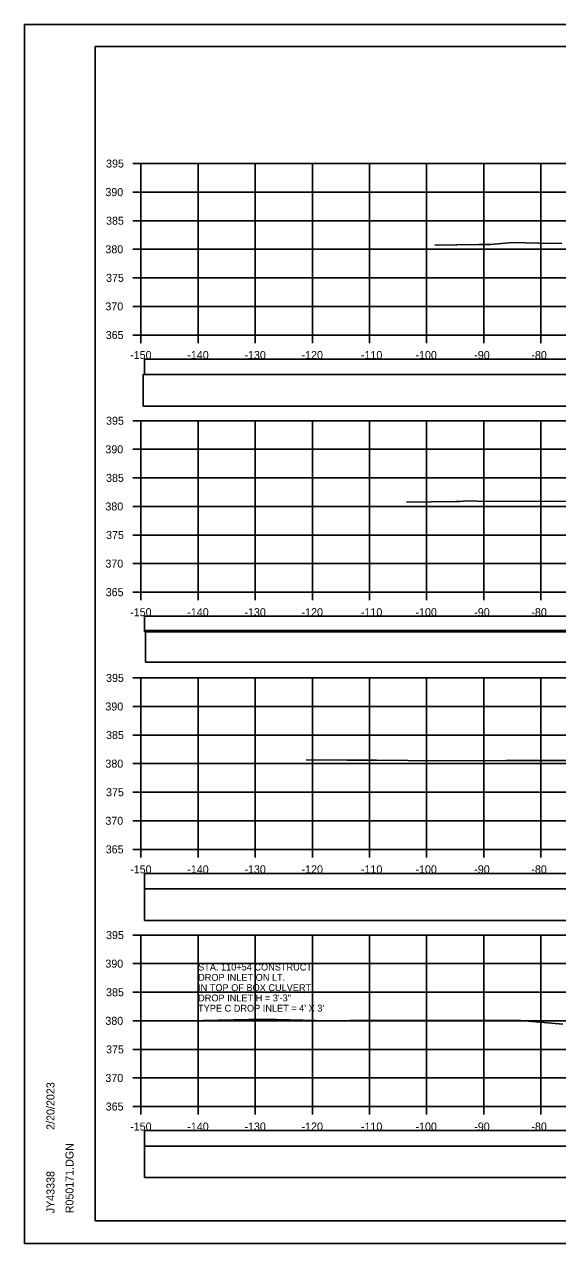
# Model space of a CAD drawing. Extents: x -37291014 to -37290680, y -936053 to -933067.
# Drawn here: x -37291013.5 to -37290920.2, y -933919.9 to -933706.6 of the extents above; entities that cross this region are included whole.
import ezdxf

# ---------------------------------------------------------------- set-up
doc = ezdxf.new("R2010")
doc.units = 0
for name, color, linetype in [('Default', 7, 'Continuous'), ('R_Axis', 7, 'Continuous'), ('R_Axis Annot', 7, 'Continuous'), ('R_Border', 7, 'Continuous'), ('R_Exist Surface', 7, 'Continuous'), ('R_Grid', 7, 'Continuous'), ('R_No Plot', 7, 'Continuous'), ('R_Water Annot', 7, 'Continuous')]:
    doc.layers.add(name, color=color, linetype=linetype)

msp = doc.modelspace()

# ---------------------------------------------------------------- linework, layer by layer
at = {"layer": 'Default'}
for points in [[(-37290992.48, -933767.85), (-37290693.72, -933767.85), (-37290693.72, -933765.14), (-37290992.48, -933765.14)], [(-37290992.71, -933773.37), (-37290693.95, -933773.37), (-37290693.95, -933767.85), (-37290992.71, -933767.85)], [(-37290992.48, -933812.85), (-37290693.72, -933812.85), (-37290693.72, -933810.14), (-37290992.48, -933810.14)], [(-37290992.31, -933818.16), (-37290693.55, -933818.16), (-37290693.55, -933812.64), (-37290992.31, -933812.64)], [(-37290992.48, -933857.85), (-37290693.72, -933857.85), (-37290693.72, -933855.14), (-37290992.48, -933855.14)], [(-37290992.48, -933863.37), (-37290693.72, -933863.37), (-37290693.72, -933857.85), (-37290992.48, -933857.85)], [(-37290992.48, -933902.85), (-37290693.72, -933902.85), (-37290693.72, -933900.14), (-37290992.48, -933900.14)], [(-37290992.48, -933908.37), (-37290693.72, -933908.37), (-37290693.72, -933902.85), (-37290992.48, -933902.85)]]:
    msp.add_lwpolyline(points, close=True, dxfattribs=at)
at = {"layer": 'R_Axis'}
for p, q in [((-37290994.5, -933730.94), (-37290993.1, -933730.94)), ((-37290993.1, -933760.94), (-37290993.1, -933730.94)), ((-37290994.5, -933735.94), (-37290993.1, -933735.94)), ((-37290994.5, -933740.94), (-37290993.1, -933740.94)), ((-37290994.5, -933745.94), (-37290993.1, -933745.94)), ((-37290994.5, -933750.94), (-37290993.1, -933750.94)), ((-37290994.5, -933755.94), (-37290993.1, -933755.94)), ((-37290994.5, -933760.94), (-37290993.1, -933760.94)), ((-37290993.1, -933760.94), (-37290693.1, -933760.94)), ((-37290993.1, -933762.34), (-37290993.1, -933760.94)), ((-37290983.1, -933762.34), (-37290983.1, -933760.94)), ((-37290973.1, -933762.34), (-37290973.1, -933760.94)), ((-37290963.1, -933762.34), (-37290963.1, -933760.94)), ((-37290953.1, -933762.34), (-37290953.1, -933760.94)), ((-37290943.1, -933762.34), (-37290943.1, -933760.94)), ((-37290933.1, -933762.34), (-37290933.1, -933760.94)), ((-37290923.1, -933762.34), (-37290923.1, -933760.94)), ((-37290994.5, -933775.94), (-37290993.1, -933775.94)), ((-37290993.1, -933805.94), (-37290993.1, -933775.94)), ((-37290994.5, -933780.94), (-37290993.1, -933780.94)), ((-37290994.5, -933785.94), (-37290993.1, -933785.94)), ((-37290994.5, -933790.94), (-37290993.1, -933790.94)), ((-37290994.5, -933795.94), (-37290993.1, -933795.94)), ((-37290994.5, -933800.94), (-37290993.1, -933800.94)), ((-37290994.5, -933805.94), (-37290993.1, -933805.94)), ((-37290993.1, -933805.94), (-37290693.1, -933805.94)), ((-37290993.1, -933807.34), (-37290993.1, -933805.94)), ((-37290983.1, -933807.34), (-37290983.1, -933805.94)), ((-37290973.1, -933807.34), (-37290973.1, -933805.94)), ((-37290963.1, -933807.34), (-37290963.1, -933805.94)), ((-37290953.1, -933807.34), (-37290953.1, -933805.94)), ((-37290943.1, -933807.34), (-37290943.1, -933805.94)), ((-37290933.1, -933807.34), (-37290933.1, -933805.94)), ((-37290923.1, -933807.34), (-37290923.1, -933805.94)), ((-37290994.5, -933820.94), (-37290993.1, -933820.94)), ((-37290993.1, -933850.94), (-37290993.1, -933820.94)), ((-37290994.5, -933825.94), (-37290993.1, -933825.94)), ((-37290994.5, -933830.94), (-37290993.1, -933830.94)), ((-37290994.5, -933835.94), (-37290993.1, -933835.94)), ((-37290994.5, -933840.94), (-37290993.1, -933840.94)), ((-37290994.5, -933845.94), (-37290993.1, -933845.94)), ((-37290994.5, -933850.94), (-37290993.1, -933850.94)), ((-37290993.1, -933850.94), (-37290693.1, -933850.94)), ((-37290993.1, -933852.34), (-37290993.1, -933850.94)), ((-37290983.1, -933852.34), (-37290983.1, -933850.94)), ((-37290973.1, -933852.34), (-37290973.1, -933850.94)), ((-37290963.1, -933852.34), (-37290963.1, -933850.94)), ((-37290953.1, -933852.34), (-37290953.1, -933850.94)), ((-37290943.1, -933852.34), (-37290943.1, -933850.94)), ((-37290933.1, -933852.34), (-37290933.1, -933850.94)), ((-37290923.1, -933852.34), (-37290923.1, -933850.94)), ((-37290994.5, -933865.94), (-37290993.1, -933865.94)), ((-37290993.1, -933895.94), (-37290993.1, -933865.94)), ((-37290994.5, -933870.94), (-37290993.1, -933870.94)), ((-37290994.5, -933875.94), (-37290993.1, -933875.94)), ((-37290994.5, -933880.94), (-37290993.1, -933880.94)), ((-37290994.5, -933885.94), (-37290993.1, -933885.94)), ((-37290994.5, -933890.94), (-37290993.1, -933890.94)), ((-37290994.5, -933895.94), (-37290993.1, -933895.94)), ((-37290993.1, -933895.94), (-37290693.1, -933895.94)), ((-37290993.1, -933897.34), (-37290993.1, -933895.94)), ((-37290983.1, -933897.34), (-37290983.1, -933895.94)), ((-37290973.1, -933897.34), (-37290973.1, -933895.94)), ((-37290963.1, -933897.34), (-37290963.1, -933895.94)), ((-37290953.1, -933897.34), (-37290953.1, -933895.94)), ((-37290943.1, -933897.34), (-37290943.1, -933895.94)), ((-37290933.1, -933897.34), (-37290933.1, -933895.94)), ((-37290923.1, -933897.34), (-37290923.1, -933895.94))]:
    msp.add_line(p, q, dxfattribs=at)
at = {"layer": 'R_Border'}
for p, q in [((-37291001.1, -933710.48), (-37290684.92, -933710.48)), ((-37291001.1, -933915.94), (-37291001.1, -933710.48)), ((-37291001.1, -933915.94), (-37291001.1, -933915.94)), ((-37290684.92, -933915.94), (-37291001.1, -933915.94))]:
    msp.add_line(p, q, dxfattribs=at)
at = {"layer": 'R_Exist Surface'}
for points in [[(-37290941.66, -933745.22), (-37290933.97, -933745.1), (-37290931.94, -933745.1), (-37290928.04, -933744.74), (-37290923.43, -933744.89), (-37290922.54, -933744.92), (-37290919.45, -933744.9)], [(-37290946.61, -933790.21), (-37290938.01, -933790.08), (-37290937.34, -933790.08), (-37290936.05, -933789.96), (-37290934.22, -933790.02), (-37290921.45, -933790.05), (-37290917.47, -933790.04)], [(-37290964.19, -933835.25), (-37290957.03, -933835.36), (-37290951.87, -933835.35), (-37290940.86, -933835.44), (-37290929.18, -933835.4), (-37290916.8, -933835.38)], [(-37290993.1, -933880.99), (-37290991.13, -933880.92), (-37290989.15, -933880.92), (-37290984.83, -933880.93), (-37290971.68, -933880.68), (-37290962.48, -933880.91), (-37290961.55, -933880.92), (-37290956.47, -933880.91), (-37290940.54, -933880.89), (-37290926.63, -933880.87), (-37290919.27, -933881.55)]]:
    msp.add_lwpolyline(points, dxfattribs=at)
at = {"layer": 'R_Grid'}
for p, q in [((-37290993.1, -933730.94), (-37290693.1, -933730.94)), ((-37290993.1, -933760.94), (-37290993.1, -933730.94)), ((-37290983.1, -933760.94), (-37290983.1, -933730.94)), ((-37290973.1, -933760.94), (-37290973.1, -933730.94)), ((-37290963.1, -933760.94), (-37290963.1, -933730.94)), ((-37290953.1, -933760.94), (-37290953.1, -933730.94)), ((-37290943.1, -933760.94), (-37290943.1, -933730.94)), ((-37290933.1, -933760.94), (-37290933.1, -933730.94)), ((-37290923.1, -933760.94), (-37290923.1, -933730.94)), ((-37290993.1, -933735.94), (-37290693.1, -933735.94)), ((-37290993.1, -933740.94), (-37290693.1, -933740.94)), ((-37290993.1, -933745.94), (-37290693.1, -933745.94)), ((-37290993.1, -933750.94), (-37290693.1, -933750.94)), ((-37290993.1, -933755.94), (-37290693.1, -933755.94)), ((-37290993.1, -933760.94), (-37290693.1, -933760.94)), ((-37290993.1, -933775.94), (-37290693.1, -933775.94)), ((-37290993.1, -933805.94), (-37290993.1, -933775.94)), ((-37290983.1, -933805.94), (-37290983.1, -933775.94)), ((-37290973.1, -933805.94), (-37290973.1, -933775.94)), ((-37290963.1, -933805.94), (-37290963.1, -933775.94)), ((-37290953.1, -933805.94), (-37290953.1, -933775.94)), ((-37290943.1, -933805.94), (-37290943.1, -933775.94)), ((-37290933.1, -933805.94), (-37290933.1, -933775.94)), ((-37290923.1, -933805.94), (-37290923.1, -933775.94)), ((-37290993.1, -933780.94), (-37290693.1, -933780.94)), ((-37290993.1, -933785.94), (-37290693.1, -933785.94)), ((-37290993.1, -933790.94), (-37290693.1, -933790.94)), ((-37290993.1, -933795.94), (-37290693.1, -933795.94)), ((-37290993.1, -933800.94), (-37290693.1, -933800.94)), ((-37290993.1, -933805.94), (-37290693.1, -933805.94)), ((-37290993.1, -933820.94), (-37290693.1, -933820.94)), ((-37290993.1, -933850.94), (-37290993.1, -933820.94)), ((-37290983.1, -933850.94), (-37290983.1, -933820.94)), ((-37290973.1, -933850.94), (-37290973.1, -933820.94)), ((-37290963.1, -933850.94), (-37290963.1, -933820.94)), ((-37290953.1, -933850.94), (-37290953.1, -933820.94)), ((-37290943.1, -933850.94), (-37290943.1, -933820.94)), ((-37290933.1, -933850.94), (-37290933.1, -933820.94)), ((-37290923.1, -933850.94), (-37290923.1, -933820.94)), ((-37290993.1, -933825.94), (-37290693.1, -933825.94)), ((-37290993.1, -933830.94), (-37290693.1, -933830.94)), ((-37290993.1, -933835.94), (-37290693.1, -933835.94)), ((-37290993.1, -933840.94), (-37290693.1, -933840.94)), ((-37290993.1, -933845.94), (-37290693.1, -933845.94)), ((-37290993.1, -933850.94), (-37290693.1, -933850.94)), ((-37290993.1, -933865.94), (-37290693.1, -933865.94)), ((-37290993.1, -933895.94), (-37290993.1, -933865.94)), ((-37290983.1, -933895.94), (-37290983.1, -933865.94)), ((-37290973.1, -933895.94), (-37290973.1, -933865.94)), ((-37290963.1, -933895.94), (-37290963.1, -933865.94)), ((-37290953.1, -933895.94), (-37290953.1, -933865.94)), ((-37290943.1, -933895.94), (-37290943.1, -933865.94)), ((-37290933.1, -933895.94), (-37290933.1, -933865.94)), ((-37290923.1, -933895.94), (-37290923.1, -933865.94)), ((-37290993.1, -933870.94), (-37290693.1, -933870.94)), ((-37290993.1, -933875.94), (-37290693.1, -933875.94)), ((-37290993.1, -933880.94), (-37290693.1, -933880.94)), ((-37290993.1, -933885.94), (-37290693.1, -933885.94)), ((-37290993.1, -933890.94), (-37290693.1, -933890.94)), ((-37290993.1, -933895.94), (-37290693.1, -933895.94))]:
    msp.add_line(p, q, dxfattribs=at)
at = {"layer": 'R_No Plot'}
for p, q in [((-37291013.5, -933706.59), (-37290680.17, -933706.59)), ((-37291013.5, -933919.92), (-37290680.17, -933919.92))]:
    msp.add_line(p, q, dxfattribs=at)
for points in [[(-37291013.51, -933706.59), (-37290680.17, -933706.59), (-37290680.17, -933919.93), (-37291013.51, -933919.93)], [(-37290767.18, -933710.48), (-37290747.56, -933710.48), (-37290747.56, -933720.36), (-37290731.45, -933720.36), (-37290708.25, -933720.36), (-37290708.25, -933744.7), (-37290684.92, -933744.7), (-37290684.92, -933915.94), (-37291001.1, -933915.94), (-37291001.1, -933710.48)]]:
    msp.add_lwpolyline(points, close=True, dxfattribs=at)

# ---------------------------------------------------------------- texts
at = {"layer": 'R_Axis Annot'}
for s, p in [('395', (-37290999.21, -933731.64)), ('390', (-37290999.33, -933736.64)), ('385', (-37290999.21, -933741.64)), ('380', (-37290999.33, -933746.64)), ('375', (-37290999.21, -933751.64)), ('370', (-37290999.33, -933756.64)), ('365', (-37290999.27, -933761.64)), ('-150', (-37290994.99, -933765.14)), ('-140', (-37290984.99, -933765.14)), ('-130', (-37290974.99, -933765.14)), ('-120', (-37290964.99, -933765.14)), ('-110', (-37290954.6, -933765.14)), ('-100', (-37290945.05, -933765.14)), ('-90', (-37290934.76, -933765.14)), ('-80', (-37290924.76, -933765.14)), ('395', (-37290999.21, -933776.64)), ('390', (-37290999.33, -933781.64)), ('385', (-37290999.21, -933786.64)), ('380', (-37290999.33, -933791.64)), ('375', (-37290999.21, -933796.64)), ('370', (-37290999.33, -933801.64)), ('365', (-37290999.27, -933806.64)), ('-150', (-37290994.99, -933810.14)), ('-140', (-37290984.99, -933810.14)), ('-130', (-37290974.99, -933810.14)), ('-120', (-37290964.99, -933810.14)), ('-110', (-37290954.6, -933810.14)), ('-100', (-37290945.05, -933810.14)), ('-90', (-37290934.76, -933810.14)), ('-80', (-37290924.76, -933810.14)), ('395', (-37290999.21, -933821.64)), ('390', (-37290999.33, -933826.64)), ('385', (-37290999.21, -933831.64)), ('380', (-37290999.33, -933836.64)), ('375', (-37290999.21, -933841.64)), ('370', (-37290999.33, -933846.64)), ('365', (-37290999.27, -933851.64)), ('-150', (-37290994.99, -933855.14)), ('-140', (-37290984.99, -933855.14)), ('-130', (-37290974.99, -933855.14)), ('-120', (-37290964.99, -933855.14)), ('-110', (-37290954.6, -933855.14)), ('-100', (-37290945.05, -933855.14)), ('-90', (-37290934.76, -933855.14)), ('-80', (-37290924.76, -933855.14)), ('395', (-37290999.21, -933866.64)), ('390', (-37290999.33, -933871.64)), ('385', (-37290999.21, -933876.64)), ('380', (-37290999.33, -933881.64)), ('375', (-37290999.21, -933886.64)), ('370', (-37290999.33, -933891.64)), ('365', (-37290999.27, -933896.64)), ('-150', (-37290994.99, -933900.14)), ('-140', (-37290984.99, -933900.14)), ('-130', (-37290974.99, -933900.14)), ('-120', (-37290964.99, -933900.14)), ('-110', (-37290954.6, -933900.14)), ('-100', (-37290945.05, -933900.14)), ('-90', (-37290934.76, -933900.14)), ('-80', (-37290924.76, -933900.14))]:
    msp.add_text(s, height=1.4, dxfattribs=at).set_placement(p)
at = {"layer": 'R_Border'}
for s, p in [('2/20/2023', (-37291008.24, -933900.02)), ('R050171.DGN', (-37291004.91, -933914.62)), ('JY43338', (-37291008.24, -933914.62))]:
    msp.add_text(s, height=1.4, rotation=90, dxfattribs=at).set_placement(p)
at = {"layer": 'R_Water Annot'}
for s, p in [('STA. 110+54 CONSTRUCT', (-37290983.1, -933872.14)), ('DROP INLET ON LT.', (-37290983.1, -933873.94)), ('IN TOP OF BOX CULVERT', (-37290983.1, -933875.74)), ('DROP INLET H = 3\'-3"', (-37290983.1, -933877.54)), ("TYPE C DROP INLET = 4' X 3'", (-37290983.1, -933879.34))]:
    msp.add_text(s, height=1.2, dxfattribs=at).set_placement(p)

doc.saveas('drawing.dxf')
